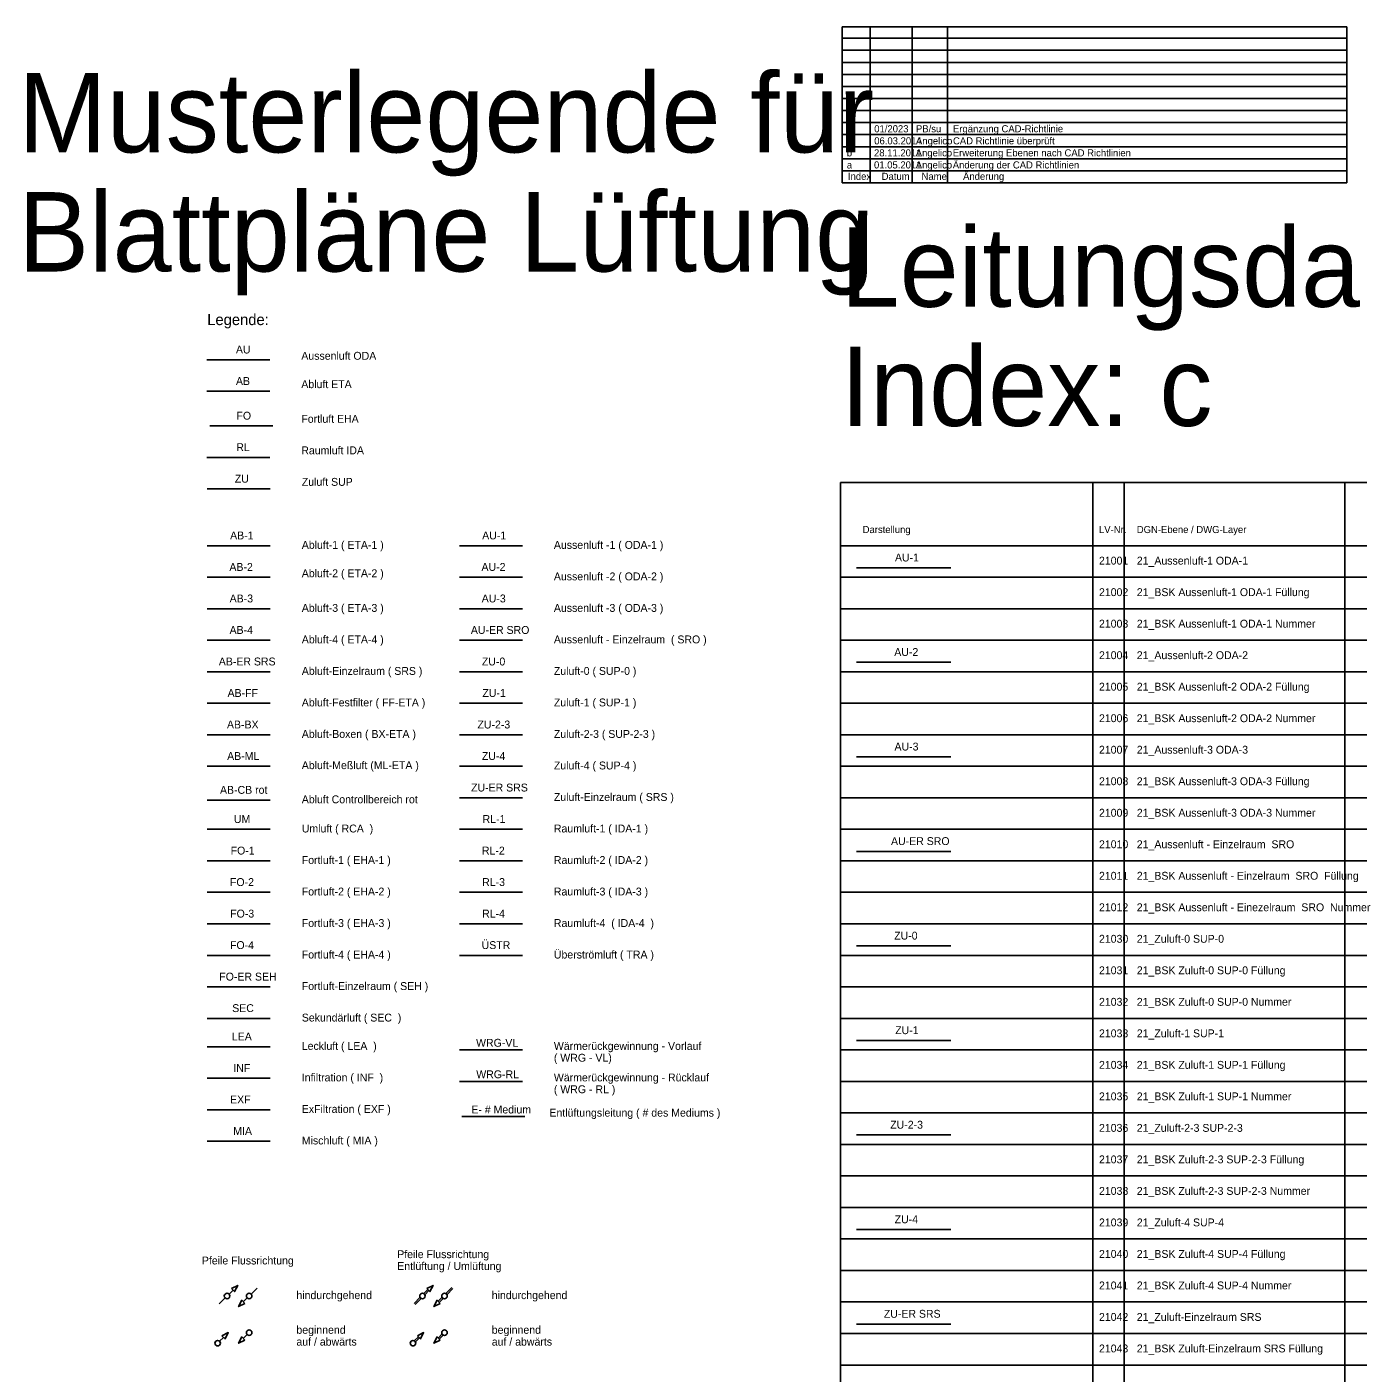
# Model space of a CAD drawing. Extents: x -26 to 55, y -9 to 161.
# Drawn here: x -25.82 to 16.42, y 118.74 to 161.46 of the extents above; entities that cross this region are included whole.
import ezdxf

# ---------------------------------------------------------------- set-up
doc = ezdxf.new("R2010")
doc.units = 0
for name, color, linetype in [('21_Abluft ETA', 7, 'Continuous'), ('21_Aussenluft - Einzelraum SRO', 7, 'Continuous'), ('21_Aussenluft ODA', 7, 'Continuous'), ('21_Aussenluft-1 ODA-1', 7, 'Continuous'), ('21_Aussenluft-2 ODA-2', 7, 'Continuous'), ('21_Aussenluft-3 ODA-3', 7, 'Continuous'), ('21_Fortluft EHA', 7, 'Continuous'), ('21_Raumluft-1 IDA-1', 7, 'Continuous'), ('21_Zuluft-0 SUP-0', 7, 'Continuous'), ('21_Zuluft-1 SUP-1', 7, 'Continuous'), ('21_Zuluft-2-3 SUP-2-3', 7, 'Continuous'), ('21_Zuluft-4 SUP-4', 7, 'Continuous'), ('21_Zuluft-Einzelraum SRS', 7, 'Continuous'), ('90_Plankopf', 7, 'Continuous'), ('Default', 7, 'Continuous')]:
    doc.layers.add(name, color=color, linetype=linetype)

msp = doc.modelspace()

# ---------------------------------------------------------------- linework, layer by layer
at = {"layer": '21_Abluft ETA'}
msp.add_line((-20.115, 149.9), (-18.115, 149.9), dxfattribs=at)
at = {"layer": '21_Aussenluft - Einzelraum SRO'}
msp.add_line((0.5, 135.3), (3.5, 135.3), dxfattribs=at)
at = {"layer": '21_Aussenluft ODA'}
msp.add_line((-20.115, 150.9), (-18.115, 150.9), dxfattribs=at)
at = {"layer": '21_Aussenluft-1 ODA-1'}
msp.add_line((0.5, 144.3), (3.5, 144.3), dxfattribs=at)
at = {"layer": '21_Aussenluft-2 ODA-2'}
msp.add_line((0.5, 141.3), (3.5, 141.3), dxfattribs=at)
at = {"layer": '21_Aussenluft-3 ODA-3'}
msp.add_line((0.5, 138.3), (3.5, 138.3), dxfattribs=at)
at = {"layer": '21_Fortluft EHA'}
msp.add_line((-20.015, 148.8), (-18.015, 148.8), dxfattribs=at)
at = {"layer": '21_Raumluft-1 IDA-1'}
msp.add_line((-20.115, 147.8), (-18.115, 147.8), dxfattribs=at)
at = {"layer": '21_Zuluft-0 SUP-0'}
msp.add_line((0.5, 132.3), (3.5, 132.3), dxfattribs=at)
at = {"layer": '21_Zuluft-1 SUP-1'}
msp.add_line((0.5, 129.3), (3.5, 129.3), dxfattribs=at)
at = {"layer": '21_Zuluft-2-3 SUP-2-3'}
for p, q in [((-20.1, 146.8), (-18.1, 146.8)), ((0.5, 126.3), (3.5, 126.3))]:
    msp.add_line(p, q, dxfattribs=at)
at = {"layer": '21_Zuluft-4 SUP-4'}
msp.add_line((0.5, 123.3), (3.5, 123.3), dxfattribs=at)
at = {"layer": '21_Zuluft-Einzelraum SRS'}
msp.add_line((0.5, 120.3), (3.5, 120.3), dxfattribs=at)
at = {"layer": '90_Plankopf'}
for p, q in [((-20.1, 145), (-18.1, 145)), ((-12.1, 145), (-10.1, 145)), ((-20.1, 144), (-18.1, 144)), ((-12.1, 144), (-10.1, 144)), ((-20.1, 143), (-18.1, 143)), ((-12.1, 143), (-10.1, 143)), ((-20.1, 142), (-18.1, 142)), ((-12.1, 142), (-10.1, 142)), ((-20.1, 141), (-18.1, 141)), ((-12.1, 141), (-10.1, 141)), ((-20.1, 140), (-18.1, 140)), ((-12.1, 140), (-10.1, 140)), ((-20.1, 139), (-18.1, 139)), ((-12.1, 139), (-10.1, 139)), ((-20.1, 138), (-18.1, 138)), ((-12.1, 138), (-10.1, 138)), ((-20.1, 136.926), (-18.1, 136.926)), ((-12.1, 137), (-10.1, 137)), ((-20.1, 136), (-18.1, 136)), ((-12.1, 136), (-10.1, 136)), ((-20.1, 135), (-18.1, 135)), ((-12.1, 135), (-10.1, 135)), ((-20.1, 134), (-18.1, 134)), ((-12.1, 134), (-10.1, 134)), ((-20.1, 133), (-18.1, 133)), ((-12.1, 133), (-10.1, 133)), ((-20.1, 132), (-18.1, 132)), ((-12.1, 132), (-10.1, 132)), ((-20.1, 131), (-18.1, 131)), ((-20.1, 130), (-18.1, 130)), ((-20.1, 129.1), (-18.1, 129.1)), ((-12.1, 129), (-10.1, 129)), ((-20.1, 128.1), (-18.1, 128.1)), ((-12.1, 128), (-10.1, 128)), ((-20.1, 127.1), (-18.1, 127.1)), ((-12.019, 126.882), (-10.019, 126.882)), ((-20.1, 126.1), (-18.1, 126.1)), ((-19.409, 121.252), (-19.283, 121.378)), ((-18.52, 121.442), (-18.709, 121.252)), ((-13.229, 121.268), (-13.101, 121.396)), ((-13.194, 121.232), (-13.066, 121.36)), ((-12.338, 121.459), (-12.529, 121.268)), ((-12.302, 121.424), (-12.494, 121.232)), ((-19.722, 120.94), (-19.533, 121.129)), ((-18.833, 121.129), (-18.958, 121.003)), ((-13.539, 120.957), (-13.348, 121.149)), ((-13.504, 120.922), (-13.312, 121.114)), ((-12.648, 121.149), (-12.776, 121.021)), ((-12.612, 121.114), (-12.741, 120.985)), ((-19.709, 119.752), (-19.583, 119.878)), ((-18.833, 119.965), (-18.958, 119.84)), ((-13.529, 119.768), (-13.401, 119.896)), ((-13.494, 119.732), (-13.366, 119.86)), ((-12.648, 119.986), (-12.776, 119.857)), ((-12.612, 119.95), (-12.741, 119.822))]:
    msp.add_line(p, q, dxfattribs=at)
for points in [[(-19.333, 121.428), (-19.234, 121.328), (-19.134, 121.527)], [(-13.133, 121.428), (-13.034, 121.328), (-12.934, 121.527)], [(-18.909, 120.953), (-19.008, 121.053), (-19.108, 120.854)], [(-12.709, 120.953), (-12.808, 121.053), (-12.908, 120.854)], [(-19.633, 119.928), (-19.534, 119.828), (-19.434, 120.027)], [(-18.909, 119.79), (-19.008, 119.889), (-19.108, 119.691)], [(-13.433, 119.928), (-13.334, 119.828), (-13.234, 120.027)], [(-12.709, 119.79), (-12.808, 119.889), (-12.908, 119.691)]]:
    msp.add_lwpolyline(points, close=True, dxfattribs=at)
for centre in [(-19.471, 121.191), (-18.771, 121.191), (-13.271, 121.191), (-12.571, 121.191), (-18.771, 120.027), (-12.571, 120.027), (-19.771, 119.691), (-13.571, 119.691)]:
    msp.add_circle(centre, 0.0875, dxfattribs=at)
at = {"layer": 'Default'}
for p, q in [((0.052, 156.513), (0.052, 161.462)), ((0.052, 161.462), (16.061, 161.462)), ((0.052, 161.103), (16.061, 161.103)), ((0.942, 156.513), (0.942, 161.462)), ((2.276, 156.513), (2.276, 161.462)), ((3.388, 156.513), (3.388, 161.462)), ((16.061, 156.513), (16.061, 161.462)), ((0.052, 160.72), (16.061, 160.72)), ((0.052, 160.338), (16.061, 160.338)), ((0.052, 159.955), (16.061, 159.955)), ((0.052, 159.573), (16.061, 159.573)), ((0.052, 159.19), (16.061, 159.19)), ((0.052, 158.808), (16.061, 158.808)), ((0.052, 158.425), (16.061, 158.425)), ((0.052, 158.043), (16.061, 158.043)), ((0.052, 157.66), (16.061, 157.66)), ((0.052, 157.278), (16.061, 157.278)), ((0.052, 156.895), (16.061, 156.895)), ((0.052, 156.513), (16.061, 156.513)), ((0.052, 156.513), (16.061, 156.513)), ((0, 147), (0, 0)), ((0, 147), (33.6, 147)), ((8, 147), (8, 0)), ((9, 147), (9, 0)), ((16, 147), (16, 0)), ((0, 145), (33.6, 145)), ((0, 144), (33.6, 144)), ((0, 143), (33.6, 143)), ((0, 142), (33.6, 142)), ((0, 141), (33.6, 141)), ((0, 140), (33.6, 140)), ((0, 139), (33.6, 139)), ((0, 138), (33.6, 138)), ((0, 137), (33.6, 137)), ((0, 136), (33.6, 136)), ((0, 135), (33.6, 135)), ((0, 134), (33.6, 134)), ((0, 133), (33.6, 133)), ((0, 132), (33.6, 132)), ((0, 131), (33.6, 131)), ((0, 130), (33.6, 130)), ((0, 129), (33.6, 129)), ((0, 128), (33.6, 128)), ((0, 127), (33.6, 127)), ((0, 126), (33.6, 126)), ((0, 125), (33.6, 125)), ((0, 124), (33.6, 124)), ((0, 123), (33.6, 123)), ((0, 122), (33.6, 122)), ((0, 121), (33.6, 121)), ((0, 120), (33.6, 120)), ((0, 119), (33.6, 119))]:
    msp.add_line(p, q, dxfattribs=at)

# ---------------------------------------------------------------- texts
at = {"layer": '21_Abluft ETA'}
msp.add_text('AB', height=0.25, dxfattribs=at).set_placement((-19.19, 150.1))
at = {"layer": '21_Aussenluft - Einzelraum SRO'}
msp.add_text('AU-ER SRO', height=0.25, dxfattribs=at).set_placement((1.6, 135.5))
at = {"layer": '21_Aussenluft ODA'}
msp.add_text('AU', height=0.25, dxfattribs=at).set_placement((-19.19, 151.1))
at = {"layer": '21_Aussenluft-1 ODA-1'}
msp.add_text('AU-1', height=0.25, dxfattribs=at).set_placement((1.725, 144.5))
at = {"layer": '21_Aussenluft-2 ODA-2'}
msp.add_text('AU-2', height=0.25, dxfattribs=at).set_placement((1.703, 141.5))
at = {"layer": '21_Aussenluft-3 ODA-3'}
msp.add_text('AU-3', height=0.25, dxfattribs=at).set_placement((1.71, 138.5))
at = {"layer": '21_Fortluft EHA'}
msp.add_text('FO', height=0.25, dxfattribs=at).set_placement((-19.173, 149))
at = {"layer": '21_Raumluft-1 IDA-1'}
msp.add_text('RL', height=0.25, dxfattribs=at).set_placement((-19.177, 148))
at = {"layer": '21_Zuluft-0 SUP-0'}
msp.add_text('ZU-0', height=0.25, dxfattribs=at).set_placement((1.7, 132.5))
at = {"layer": '21_Zuluft-1 SUP-1'}
msp.add_text('ZU-1', height=0.25, dxfattribs=at).set_placement((1.732, 129.5))
at = {"layer": '21_Zuluft-2-3 SUP-2-3'}
for s, p in [('ZU', (-19.226, 147)), ('ZU-2-3', (1.574, 126.5))]:
    msp.add_text(s, height=0.25, dxfattribs=at).set_placement(p)
at = {"layer": '21_Zuluft-4 SUP-4'}
msp.add_text('ZU-4', height=0.25, dxfattribs=at).set_placement((1.715, 123.5))
at = {"layer": '21_Zuluft-Einzelraum SRS'}
msp.add_text('ZU-ER SRS', height=0.25, dxfattribs=at).set_placement((1.372, 120.5))
at = {"layer": '90_Plankopf'}
for s, height, p in [('Legende:', 0.35, (-20.1, 152)), ('AB-1', 0.25, (-19.375, 145.2)), ('AU-1', 0.25, (-11.375, 145.2)), ('Abluft-1 ( ETA-1 )', 0.25, (-17.1, 144.9)), ('Aussenluft -1 ( ODA-1 )', 0.25, (-9.1, 144.9)), ('AB-2', 0.25, (-19.397, 144.2)), ('AU-2', 0.25, (-11.397, 144.2)), ('Abluft-2 ( ETA-2 )', 0.25, (-17.1, 144)), ('Aussenluft -2 ( ODA-2 )', 0.25, (-9.1, 143.9)), ('AB-3', 0.25, (-19.39, 143.2)), ('Abluft-3 ( ETA-3 )', 0.25, (-17.1, 142.9)), ('AU-3', 0.25, (-11.39, 143.2)), ('Aussenluft -3 ( ODA-3 )', 0.25, (-9.1, 142.9)), ('AB-4', 0.25, (-19.392, 142.2)), ('AU-ER SRO', 0.25, (-11.734, 142.2)), ('Abluft-4 ( ETA-4 )', 0.25, (-17.1, 141.9)), ('Aussenluft - Einzelraum  ( SRO )', 0.25, (-9.1, 141.9)), ('AB-ER SRS', 0.25, (-19.734, 141.2)), ('ZU-0', 0.25, (-11.385, 141.2)), ('Abluft-Einzelraum ( SRS )', 0.25, (-17.1, 140.9)), ('Zuluft-0 ( SUP-0 )', 0.25, (-9.1, 140.9)), ('AB-FF', 0.25, (-19.456, 140.2)), ('Abluft-Festfilter ( FF-ETA )', 0.25, (-17.1, 139.9)), ('ZU-1', 0.25, (-11.368, 140.2)), ('Zuluft-1 ( SUP-1 )', 0.25, (-9.1, 139.9)), ('AB-BX', 0.25, (-19.475, 139.2)), ('ZU-2-3', 0.25, (-11.526, 139.2)), ('Abluft-Boxen ( BX-ETA )', 0.25, (-17.1, 138.9)), ('Zuluft-2-3 ( SUP-2-3 )', 0.25, (-9.1, 138.9)), ('AB-ML', 0.25, (-19.469, 138.2)), ('ZU-4', 0.25, (-11.385, 138.2)), ('Abluft-Meßluft (ML-ETA )', 0.25, (-17.1, 137.909)), ('Zuluft-4 ( SUP-4 )', 0.25, (-9.1, 137.9)), ('AB-CB rot', 0.25, (-19.696, 137.126)), ('ZU-ER SRS', 0.25, (-11.728, 137.2)), ('Zuluft-Einzelraum ( SRS )', 0.25, (-9.1, 136.9)), ('Abluft Controllbereich rot', 0.25, (-17.1, 136.826)), ('UM', 0.25, (-19.254, 136.2)), ('RL-1', 0.25, (-11.362, 136.2)), ('Umluft ( RCA  )', 0.25, (-17.1, 135.9)), ('Raumluft-1 ( IDA-1 )', 0.25, (-9.1, 135.9)), ('FO-1', 0.25, (-19.358, 135.2)), ('RL-2', 0.25, (-11.383, 135.2)), ('Fortluft-1 ( EHA-1 )', 0.25, (-17.1, 134.9)), ('Raumluft-2 ( IDA-2 )', 0.25, (-9.1, 134.9)), ('FO-2', 0.25, (-19.38, 134.2)), ('Fortluft-2 ( EHA-2 )', 0.25, (-17.1, 133.9)), ('RL-3', 0.25, (-11.377, 134.2)), ('Raumluft-3 ( IDA-3 )', 0.25, (-9.1, 133.9)), ('FO-3', 0.25, (-19.373, 133.2)), ('RL-4', 0.25, (-11.378, 133.2)), ('Fortluft-3 ( EHA-3 )', 0.25, (-17.1, 132.9)), ('Raumluft-4  ( IDA-4  )', 0.25, (-9.1, 132.9)), ('FO-4', 0.25, (-19.378, 132.2)), ('ÜSTR', 0.25, (-11.392, 132.2)), ('Fortluft-4 ( EHA-4 )', 0.25, (-17.1, 131.9)), ('Überströmluft ( TRA )', 0.25, (-9.1, 131.9)), ('FO-ER SEH', 0.25, (-19.719, 131.2)), ('Fortluft-Einzelraum ( SEH )', 0.25, (-17.1, 130.9)), ('SEC', 0.25, (-19.308, 130.2)), ('Sekundärluft ( SEC  )', 0.25, (-17.1, 129.9)), ('LEA', 0.25, (-19.318, 129.3)), ('Leckluft ( LEA  )', 0.25, (-17.1, 129)), ('WRG-VL', 0.25, (-11.569, 129.1)), ('Wärmerückgewinnung - Vorlauf ', 0.25, (-9.1, 129)), ('( WRG - VL)', 0.25, (-9.1, 128.625)), ('INF', 0.25, (-19.273, 128.3)), ('Infiltration ( INF  )', 0.25, (-17.1, 128)), ('WRG-RL', 0.25, (-11.563, 128.1)), ('Wärmerückgewinnung - Rücklauf ', 0.25, (-9.1, 128)), ('( WRG - RL )', 0.25, (-9.1, 127.625)), ('EXF ', 0.25, (-19.375, 127.3)), ('ExFiltration ( EXF )', 0.25, (-17.1, 127)), ('E- # Medium', 0.25, (-11.719, 126.982)), (' Entlüftungsleitung ( # des Mediums )', 0.25, (-9.334, 126.882)), ('MIA', 0.25, (-19.275, 126.3)), ('Mischluft ( MIA )', 0.25, (-17.1, 126)), ('Pfeile Flussrichtung', 0.25, (-14.071, 122.391)), ('Pfeile Flussrichtung', 0.25, (-20.271, 122.191)), ('Entlüftung / Umlüftung', 0.25, (-14.071, 122.016)), ('hindurchgehend', 0.25, (-17.271, 121.091)), ('hindurchgehend', 0.25, (-11.071, 121.091)), ('beginnend', 0.25, (-17.271, 119.991)), ('beginnend', 0.25, (-11.071, 119.991)), ('auf / abwärts', 0.25, (-17.271, 119.616)), ('auf / abwärts', 0.25, (-11.071, 119.616))]:
    msp.add_text(s, height=height, dxfattribs=at).set_placement(p)
at = {"layer": 'Default'}
for s, height, p in [('Musterlegende für ', 2.52, (-26.1, 157.48)), ('c     ', 0.225, (0.204, 158.118)), ('01/2023   ', 0.225, (1.067, 158.118)), ('PB/su   ', 0.225, (2.392, 158.118)), ('Ergänzung CAD-Richtlinie                                                                        ', 0.225, (3.567, 158.118)), ('-     ', 0.225, (0.204, 157.735)), ('06.03.2014', 0.225, (1.067, 157.735)), ('Angelico', 0.225, (2.392, 157.735)), ('CAD Richtlinie überprüft                                                                        ', 0.225, (3.567, 157.735)), ('b     ', 0.225, (0.197, 157.353)), ('28.11.2011', 0.225, (1.06, 157.353)), ('Angelico', 0.225, (2.385, 157.353)), ('Angelico', 0.225, (2.385, 156.97)), ('Änderung der CAD Richtlinien                                                                    ', 0.225, (3.56, 156.97)), ('Erweiterung Ebenen nach CAD Richtlinien                                                         ', 0.225, (3.56, 157.353)), ('a     ', 0.225, (0.197, 156.97)), ('Index', 0.225, (0.233, 156.608)), ('01.05.2011', 0.225, (1.06, 156.97)), ('Datum', 0.225, (1.303, 156.608)), ('Name', 0.225, (2.569, 156.608)), ('Änderung', 0.225, (3.887, 156.608)), ('Blattpläne Lüftung', 2.52, (-26.1, 153.7)), ('Leitungsdarstellung: Lüftung', 2.52, (0, 152.58)), ('Index: c', 2.52, (0, 148.8)), ('Aussenluft ODA', 0.25, (-17.115, 150.9)), ('Abluft ETA', 0.25, (-17.115, 150)), ('Fortluft EHA', 0.25, (-17.115, 148.9)), ('Raumluft IDA', 0.25, (-17.115, 147.9)), ('Zuluft SUP', 0.25, (-17.1, 146.9)), ('Darstellung', 0.225, (0.7, 145.4)), ('LV-Nr.', 0.225, (8.2, 145.4)), ('DGN-Ebene / DWG-Layer', 0.225, (9.4, 145.4)), ('21001', 0.25, (8.2, 144.4)), ('21_Aussenluft-1 ODA-1', 0.25, (9.4, 144.4)), ('21002', 0.25, (8.2, 143.4)), ('21_BSK Aussenluft-1 ODA-1 Füllung', 0.25, (9.4, 143.4)), ('21003', 0.25, (8.2, 142.4)), ('21_BSK Aussenluft-1 ODA-1 Nummer', 0.25, (9.4, 142.4)), ('21004', 0.25, (8.2, 141.4)), ('21_Aussenluft-2 ODA-2', 0.25, (9.4, 141.4)), ('21005', 0.25, (8.2, 140.4)), ('21_BSK Aussenluft-2 ODA-2 Füllung', 0.25, (9.4, 140.4)), ('21006', 0.25, (8.2, 139.4)), ('21_BSK Aussenluft-2 ODA-2 Nummer', 0.25, (9.4, 139.4)), ('21007', 0.25, (8.2, 138.4)), ('21_Aussenluft-3 ODA-3', 0.25, (9.4, 138.4)), ('21008', 0.25, (8.2, 137.4)), ('21_BSK Aussenluft-3 ODA-3 Füllung', 0.25, (9.4, 137.4)), ('21009', 0.25, (8.2, 136.4)), ('21_BSK Aussenluft-3 ODA-3 Nummer', 0.25, (9.4, 136.4)), ('21010', 0.25, (8.2, 135.4)), ('21_Aussenluft - Einzelraum  SRO ', 0.25, (9.4, 135.4)), ('21011', 0.25, (8.2, 134.4)), ('21_BSK Aussenluft - Einzelraum  SRO  Füllung', 0.25, (9.4, 134.4)), ('21012', 0.25, (8.2, 133.4)), ('21_BSK Aussenluft - Einezelraum  SRO  Nummer', 0.25, (9.4, 133.4)), ('21030', 0.25, (8.2, 132.4)), ('21_Zuluft-0 SUP-0', 0.25, (9.4, 132.4)), ('21031', 0.25, (8.2, 131.4)), ('21_BSK Zuluft-0 SUP-0 Füllung', 0.25, (9.4, 131.4)), ('21032', 0.25, (8.2, 130.4)), ('21_BSK Zuluft-0 SUP-0 Nummer', 0.25, (9.4, 130.4)), ('21033', 0.25, (8.2, 129.4)), ('21_Zuluft-1 SUP-1', 0.25, (9.4, 129.4)), ('21034', 0.25, (8.2, 128.4)), ('21_BSK Zuluft-1 SUP-1 Füllung', 0.25, (9.4, 128.4)), ('21035', 0.25, (8.2, 127.4)), ('21_BSK Zuluft-1 SUP-1 Nummer', 0.25, (9.4, 127.4)), ('21036', 0.25, (8.2, 126.4)), ('21_Zuluft-2-3 SUP-2-3', 0.25, (9.4, 126.4)), ('21037', 0.25, (8.2, 125.4)), ('21_BSK Zuluft-2-3 SUP-2-3 Füllung', 0.25, (9.4, 125.4)), ('21038', 0.25, (8.2, 124.4)), ('21_BSK Zuluft-2-3 SUP-2-3 Nummer', 0.25, (9.4, 124.4)), ('21039', 0.25, (8.2, 123.4)), ('21_Zuluft-4 SUP-4', 0.25, (9.4, 123.4)), ('21040', 0.25, (8.2, 122.4)), ('21_BSK Zuluft-4 SUP-4 Füllung', 0.25, (9.4, 122.4)), ('21041', 0.25, (8.2, 121.4)), ('21_BSK Zuluft-4 SUP-4 Nummer', 0.25, (9.4, 121.4)), ('21042', 0.25, (8.2, 120.4)), ('21_Zuluft-Einzelraum SRS', 0.25, (9.4, 120.4)), ('21043', 0.25, (8.2, 119.4)), ('21_BSK Zuluft-Einzelraum SRS Füllung', 0.25, (9.4, 119.4))]:
    msp.add_text(s, height=height, dxfattribs=at).set_placement(p)

doc.saveas('drawing.dxf')
